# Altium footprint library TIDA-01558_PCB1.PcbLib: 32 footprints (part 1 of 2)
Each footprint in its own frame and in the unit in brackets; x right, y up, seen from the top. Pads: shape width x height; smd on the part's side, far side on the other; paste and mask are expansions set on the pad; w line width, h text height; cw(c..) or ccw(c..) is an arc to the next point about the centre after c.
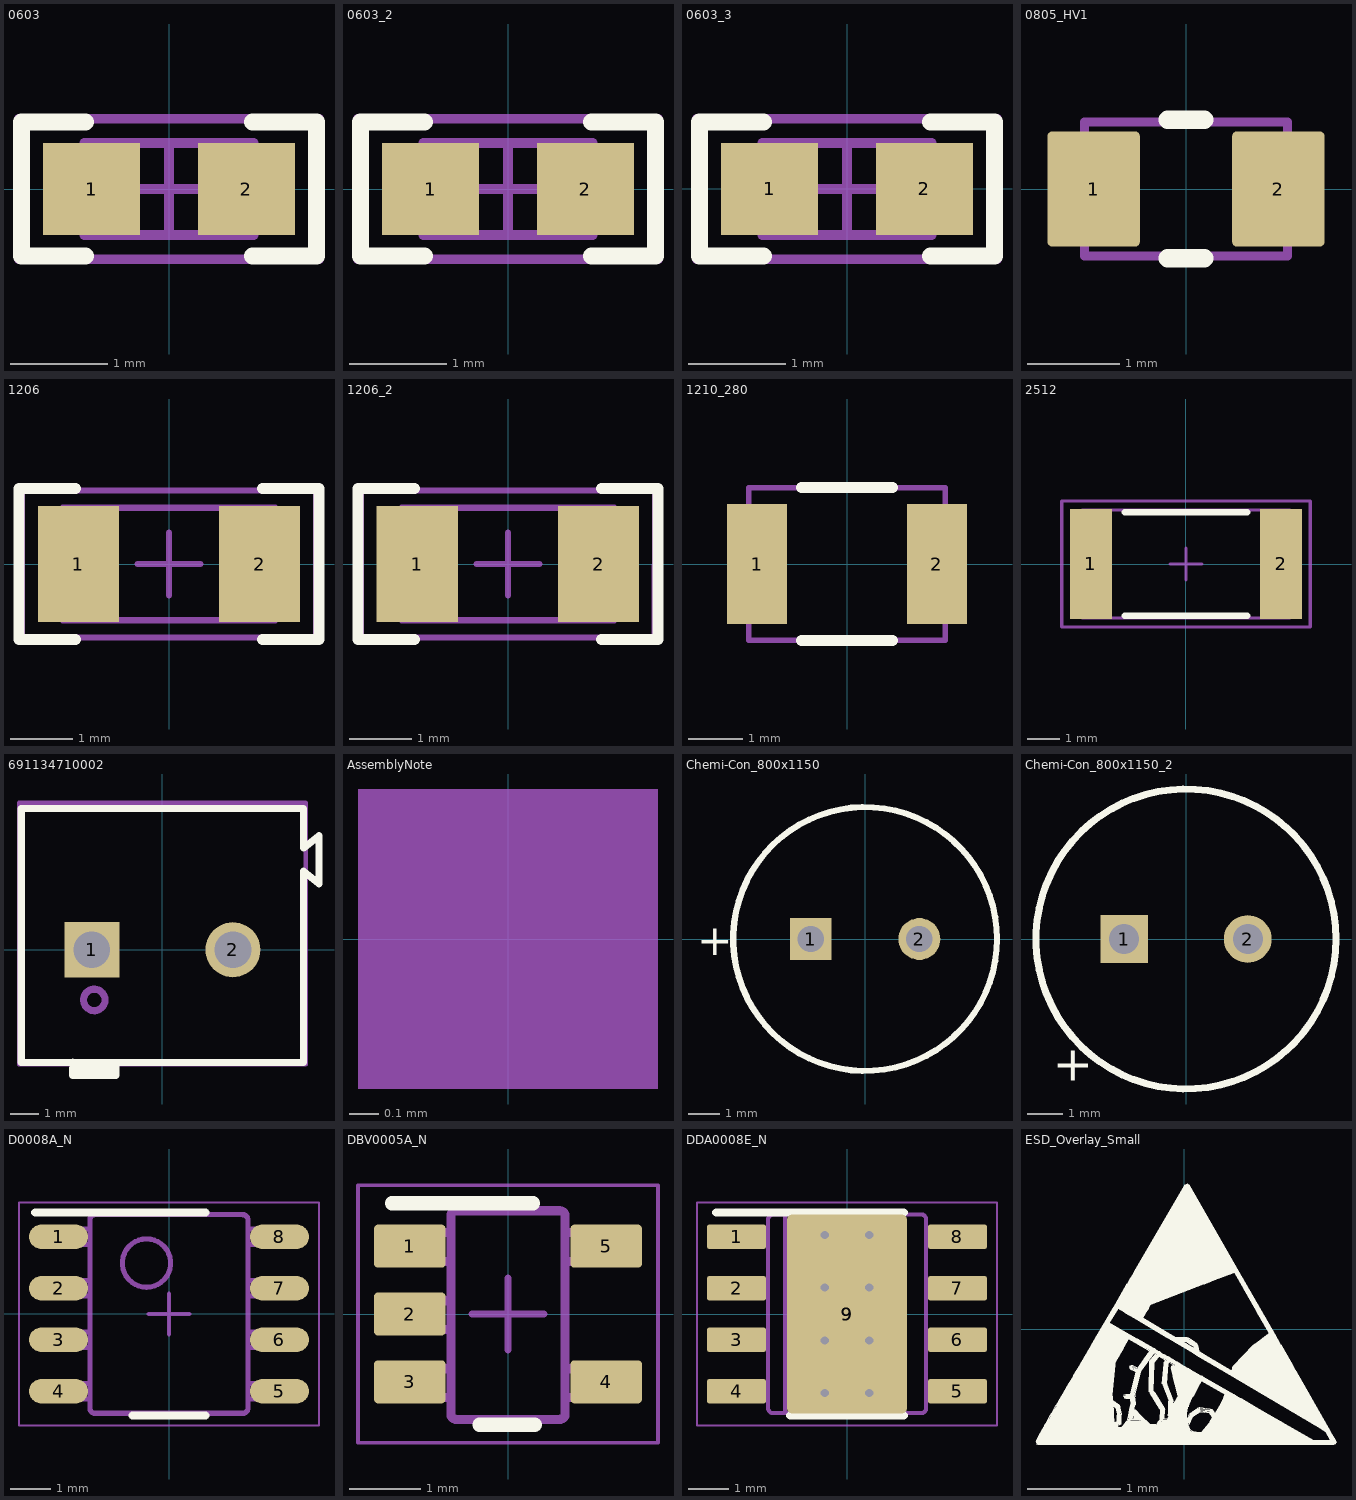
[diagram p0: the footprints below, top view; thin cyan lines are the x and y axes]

## 0603 [mm] "0603 from SM-752 data"
height 1
pads (2):
  rect 1x0.95 smd: 1(-0.8,0) 2(0.8,0)
Top Overlay:
  lines w0.178: -0.864,-0.691 -1.524,-0.691 -1.524,0.693 -0.864,0.693 ; 0.864,-0.691 1.524,-0.691 1.524,0.693 0.864,0.693
Mechanical 5:
  lines w0.1: -1.55,-0.725 1.55,-0.725 1.55,0.725 -1.55,0.725 -1.55,-0.725
  text ".Designator" at -0.933,-0.356 h0.76
Mechanical 13:
  lines w0.1: -0.55,-0.475 -0.55,0.475 ; 0.55,-0.475 0.55,0.475 ; -0.875,-0.475 -0.875,0.475 0.875,0.475 0.875,-0.475 -0.875,-0.475
Mechanical 15:
  lines w0.1: -0.475,0 0.475,0 ; 0,-0.475 0,0.475 ; -1.55,-0.725 -1.55,0.725 1.55,0.725 1.55,-0.725 -1.55,-0.725
3D body: height 1, standoff 0, extent 0.551,-0.474 0.874,0.474
3D body: height 1, standoff 0, extent -0.549,-0.474 0.549,0.474
3D body: height 1, standoff 0, extent -0.874,-0.474 -0.551,0.474

## 0603_2 [mm]
pads (2):
  rect 1x0.95 smd: 1(-0.8,0) 2(0.8,0)
Top Overlay:
  lines w0.178: -0.864,-0.691 -1.524,-0.691 -1.524,0.693 -0.864,0.693 ; 0.864,-0.691 1.524,-0.691 1.524,0.693 0.864,0.693
Mechanical 5:
  lines w0.1: -1.55,-0.725 1.55,-0.725 1.55,0.725 -1.55,0.725 -1.55,-0.725
  text ".Designator" at -0.781,-0.381 h0.76
Mechanical 13:
  lines w0.1: -0.55,-0.475 -0.55,0.475 ; 0.55,-0.475 0.55,0.475 ; -0.875,-0.475 -0.875,0.475 0.875,0.475 0.875,-0.475 -0.875,-0.475
Mechanical 15:
  lines w0.1: -0.475,0 0.475,0 ; 0,-0.475 0,0.475 ; -1.55,-0.725 -1.55,0.725 1.55,0.725 1.55,-0.725 -1.55,-0.725
3D body: height 1, standoff 0, extent 0.551,-0.474 0.874,0.474
3D body: height 1, standoff 0, extent -0.549,-0.474 0.549,0.474
3D body: height 1, standoff 0, extent -0.874,-0.474 -0.551,0.474

## 0603_3 [mm]
pads (2):
  rect 1x0.95 smd: 1(-0.8,0) 2(0.8,0)
Top Overlay:
  lines w0.178: -0.864,-0.691 -1.524,-0.691 -1.524,0.693 -0.864,0.693 ; 0.864,-0.691 1.524,-0.691 1.524,0.693 0.864,0.693
Mechanical 5:
  lines w0.1: -1.55,-0.725 1.55,-0.725 1.55,0.725 -1.55,0.725 -1.55,-0.725
  text ".Designator" at 1.016,0.381 h0.76
Mechanical 13:
  lines w0.1: -0.55,-0.475 -0.55,0.475 ; 0.55,-0.475 0.55,0.475 ; -0.875,-0.475 -0.875,0.475 0.875,0.475 0.875,-0.475 -0.875,-0.475
Mechanical 15:
  lines w0.1: -0.475,0 0.475,0 ; 0,-0.475 0,0.475 ; -1.55,-0.725 -1.55,0.725 1.55,0.725 1.55,-0.725 -1.55,-0.725
3D body: height 1, standoff 0, extent 0.551,-0.474 0.874,0.474
3D body: height 1, standoff 0, extent -0.549,-0.474 0.549,0.474
3D body: height 1, standoff 0, extent -0.874,-0.474 -0.551,0.474

## 0805_HV1 [mm] "Custom footprint based on analyzing multiple manufacturer recommendations"
height 1.45
pads (2):
  rrect10% 1x1.25 smd: 1(-1,0) 2(1,0)
Top Overlay:
  lines w0.2: -0.2,-0.75 0.2,-0.75 ; -0.2,0.75 0.2,0.75
Mechanical 5:
  lines w0.1: -1.1,-0.725 -1.1,0.725 1.1,0.725 1.1,-0.725 -1.1,-0.725
  text ".Designator" at 0.619,0.279 h0.51
3D body "0805_CapMax.stp": height 1.45, standoff 0, extent -1.1,-0.725 1.1,0.725

## 1206 [mm] "1206 from SM-752 data"
height 1.35
pads (2):
  rect 1.3x1.85 smd: 1(-1.45,0) 2(1.45,0)
Top Overlay:
  lines w0.178: -1.5,-1.21 -2.4,-1.21 -2.4,1.21 -1.5,1.21 ; 1.5,-1.21 2.4,-1.21 2.4,1.21 1.5,1.21
Mechanical 5:
  lines w0.1: -1.7,-0.9 -1.7,0.9 1.7,0.9 1.7,-0.9 -1.7,-0.9
  text ".Designator" at 0.965,0.406 h0.81
Mechanical 13:
  lines w0.1: -1.2,-0.9 -1.2,0.9 ; 1.2,-0.9 1.2,0.9 ; -1.7,-0.9 -1.7,0.9 1.7,0.9 1.7,-0.9 -1.7,-0.9
Mechanical 15:
  lines w0.1: -0.5,0 0.5,0 ; 0,-0.5 0,0.5 ; -2.35,-1.175 -2.35,1.175 2.35,1.175 2.35,-1.175 -2.35,-1.175
3D body: height 1.35, standoff 0, extent 1.201,-0.899 1.699,0.899
3D body: height 1.35, standoff 0, extent -1.199,-0.899 1.199,0.899
3D body: height 1.35, standoff 0, extent -1.699,-0.899 -1.201,0.899

## 1206_2 [mm]
pads (2):
  rect 1.3x1.85 smd: 1(-1.45,0) 2(1.45,0)
Top Overlay:
  lines w0.178: -1.5,-1.21 -2.4,-1.21 -2.4,1.21 -1.5,1.21 ; 1.5,-1.21 2.4,-1.21 2.4,1.21 1.5,1.21
Mechanical 5:
  lines w0.1: -1.7,-0.9 -1.7,0.9 1.7,0.9 1.7,-0.9 -1.7,-0.9
  text ".Designator" at -0.381,0.711 h0.81
Mechanical 13:
  lines w0.1: -1.2,-0.9 -1.2,0.9 ; 1.2,-0.9 1.2,0.9 ; -1.7,-0.9 -1.7,0.9 1.7,0.9 1.7,-0.9 -1.7,-0.9
Mechanical 15:
  lines w0.1: -0.5,0 0.5,0 ; 0,-0.5 0,0.5 ; -2.35,-1.175 -2.35,1.175 2.35,1.175 2.35,-1.175 -2.35,-1.175
3D body: height 1.35, standoff 0, extent 1.201,-0.899 1.699,0.899
3D body: height 1.35, standoff 0, extent -1.199,-0.899 1.199,0.899
3D body: height 1.35, standoff 0, extent -1.699,-0.899 -1.201,0.899

## 1210_280 [mm] "SMD, 2-Leads, Body 3.6x2.8mm, Height 2.8mm"
height 2.8
pads (2):
  rect 1.1x2.2 smd: 1(-1.65,0) 2(1.65,0)
Top Overlay:
  lines w0.2: -0.835,-1.4 0.835,-1.4 ; -0.835,1.4 0.835,1.4
Mechanical 5:
  lines w0.1: -1.8,-1.4 1.8,-1.4 1.8,1.4 -1.8,1.4 -1.8,-1.4
  text ".Designator" at 0.66,0.356 h0.8
3D body: height 2.8, standoff 0, extent 1.6,-1.4 1.8,1.4
3D body: height 2.8, standoff 0, extent -1.6,-1.4 1.6,1.4
3D body: height 2.8, standoff 0, extent -1.8,-1.4 -1.6,1.4

## 2512 [mm] "Chip Resistor, Body 6.3x3.2mm, IPC Medium Density"
height 0.71
pads (2):
  rect 1.3x3.4 smd: 1(-2.95,0) 2(2.95,0)
Top Overlay:
  lines w0.2: -1.9,-1.6 1.9,-1.6 ; -1.9,1.6 1.9,1.6
Mechanical 5:
  lines w0.1: -3.225,-1.675 -3.225,1.675 3.225,1.675 3.225,-1.675 -3.225,-1.675
  text ".Designator" at -0.889,-0.533 h1.02
Mechanical 13:
  lines w0.1: -2.463,-1.675 -2.463,1.675 ; 2.463,-1.675 2.463,1.675 ; -3.225,-1.675 -3.225,1.675 3.225,1.675 3.225,-1.675 -3.225,-1.675
Mechanical 15:
  lines w0.1: -0.5,0 0.5,0 ; 0,-0.5 0,0.5 ; -3.85,-1.95 -3.85,1.95 3.85,1.95 3.85,-1.95 -3.85,-1.95
3D body: height 0.71, standoff 0, extent 2.464,-1.674 3.224,1.674
3D body: height 0.71, standoff 0, extent -2.462,-1.674 2.462,1.674
3D body: height 0.71, standoff 0, extent -3.224,-1.674 -2.464,1.674

## 691134710002 [mm] "Serie 1347 - 5.00 mm_2 pins"
height 13
pads (2):
  rect 1.95x1.95 hole 1.3: 1(-2.5,0)
  round 1.95 hole 1.3: 2(2.5,0)
Top Overlay:
  lines w0.152: -3.175,-4.191 -3.175,-3.937 ; -1.651,-4.191 -1.651,-4
  lines w0.254: -1.651,-4.191 -3.175,-4.191 -3.175,-4.445 -1.651,-4.445 -1.651,-4 ; -5,-4 -5,5 5,5 5,3.6 5.55,4.04 5.55,2.34 5,2.78 5,-4 -5,-4
Mechanical 5:
  circle w0.254: c-2.413,-1.778 r0.381
  lines w0.152: -5.08,-4.064 -5.08,4.826 -5.08,5.207 5.08,5.207 5.08,-4.064 -5.08,-4.064
  text ".Designator" at 0.406,-0.508 h0.76
3D body "691134710002.stp": height 13.1, standoff -3.9, extent -5,-4 5.55,5

## AssemblyNote [mm] "Assembly Note"
Mechanical 5:
  rectangle: -0.508,-0.508 0.508,0.508
  text ".Designator" at -4.191,-0.508 h1.02
  text ".Comment" at 1.143,-0.508 h1.02

## Chemi-Con_800x1150 [mm] "TH, 2-Leads, Dia 8mm"
height 13
pads (2):
  rect 1.35x1.35 hole 0.85: 1(-1.75,0)
  round 1.35 hole 0.85: 2(1.75,0)
Top Overlay:
  circle w0.2: c0,0 r4.25
  text "+" at -5.416,-0.527 h1
Mechanical 5:
  circle w0.1: c0,0 r4.25
  text "+" at -5.416,-0.527 h1
  text "+" at -5.416,-0.527 h1
  text ".Designator" at 0.635,-1.27 h1.02
3D body: height 0, standoff -2.5, extent -2.048,-0.299 -1.45,0.299
3D body: height 0, standoff -2, extent 1.452,-0.299 2.05,0.299
3D body "KZN_800x1150.stp": height 13.01, standoff -4, extent -4.25,-4.249 4.26,4.25

## Chemi-Con_800x1150_2 [mm]
pads (2):
  rect 1.35x1.35 hole 0.85: 1(-1.75,0)
  round 1.35 hole 0.85: 2(1.75,0)
Top Overlay:
  circle w0.2: c0,0 r4.25
  text "+" at -3.782,-4.013 h1
Mechanical 5:
  circle w0.1: c0,0 r4.25
  text "+" at -3.782,-4.013 h1
  text "+" at -3.782,-4.013 h1
  text ".Designator" at -1.6,-0.4 h1.02
3D body: height 0, standoff -2.5, extent -2.047,-0.299 -1.45,0.3
3D body: height 0, standoff -2, extent 1.453,-0.299 2.05,0.3
3D body "KZN_800x1150.stp": height 13.01, standoff -4, extent -4.217,-4.243 4.244,4.243

## D0008A_N [mm] "SOIC, 8-Leads, Body 4.9x3.9mm, Pitch 1.27mm, IPC Medium Density"
height 1.75
pads (8):
  oval 1.45x0.6 smd: 1(-2.725,1.905) 2(-2.725,0.635) 3(-2.725,-0.635) 4(-2.725,-1.905) 5(2.725,-1.905) 6(2.725,-0.635) 7(2.725,0.635) 8(2.725,1.905)
Top Overlay:
  lines w0.2: -3.3,2.5 0.9,2.5 ; -0.9,-2.5 0.9,-2.5
Mechanical 5:
  lines w0.127: -2.375,-2.095 -2.375,-1.715 ; -2.375,-2.095 -2.589,-2.095 -3.002,-2.095 -3.002,-1.715 -2.589,-1.715 -2.375,-1.715 ; -2.375,-2.095 -1.995,-2.095 -1.952,-2.095 -1.952,-1.715 -1.995,-1.715 -2.375,-1.715 ; -2.375,-0.825 -2.375,-0.445 ; -2.375,-0.825 -2.589,-0.825 -3.002,-0.825 -3.002,-0.445 -2.589,-0.445 -2.375,-0.445 ; -2.375,-0.825 -1.995,-0.825 -1.952,-0.825 -1.952,-0.445 -1.995,-0.445 -2.375,-0.445 ; -2.375,0.445 -2.375,0.825 ; -2.375,0.445 -2.589,0.445 -3.002,0.445 -3.002,0.825 -2.589,0.825 -2.375,0.825 ; -2.375,0.445 -1.995,0.445 -1.952,0.445 -1.952,0.825 -1.995,0.825 -2.375,0.825 ; -2.375,1.715 -2.375,2.095 ; -2.375,1.715 -2.589,1.715 -3.002,1.715 -3.002,2.095 -2.589,2.095 -2.375,2.095 ; -2.375,1.715 -1.995,1.715 -1.952,1.715 -1.952,2.095 -1.995,2.095 -2.375,2.095 ; -0.332,-2.45 -0.182,-2.45 ; -0.332,-2.45 -0.182,-2.45 ; -0.332,-2.45 -1.825,-2.45 -1.826,-2.45 cw(c-1.825,-2.323) -1.952,-2.324 -1.952,-2.323 -1.952,2.323 -1.952,2.324 cw(c-1.825,2.323) -1.826,2.45 -1.825,2.45 -0.332,2.45 ; -0.332,2.45 -0.182,2.45 ; -0.332,2.45 -0.182,2.45 ; -0.182,-2.45 0.178,-2.45 ; -0.182,2.45 0.178,2.45 ; 0.178,-2.45 0.328,-2.45 ; 0.178,-2.45 0.328,-2.45 ; 0.178,2.45 0.328,2.45 ; 0.178,2.45 0.328,2.45 ; 0.328,-2.45 1.821,-2.45 1.822,-2.45 ccw(c1.821,-2.323) 1.948,-2.324 1.948,-2.323 1.948,2.323 1.948,2.324 ccw(c1.821,2.323) 1.822,2.45 1.821,2.45 0.328,2.45 ; 2.371,-2.095 2.371,-1.715 ; 2.371,-2.095 1.991,-2.095 1.948,-2.095 1.948,-1.715 1.991,-1.715 2.371,-1.715 ; 2.371,-2.095 2.585,-2.095 2.998,-2.095 2.998,-1.715 2.585,-1.715 2.371,-1.715 ; 2.371,-0.825 2.371,-0.445 ; 2.371,-0.825 1.991,-0.825 1.948,-0.825 1.948,-0.445 1.991,-0.445 2.371,-0.445 ; 2.371,-0.825 2.585,-0.825 2.998,-0.825 2.998,-0.445 2.585,-0.445 2.371,-0.445 ; 2.371,0.445 2.371,0.825 ; 2.371,0.445 1.991,0.445 1.948,0.445 1.948,0.825 1.991,0.825 2.371,0.825 ; 2.371,0.445 2.585,0.445 2.998,0.445 2.998,0.825 2.585,0.825 2.371,0.825 ; 2.371,1.715 2.371,2.095 ; 2.371,1.715 1.991,1.715 1.948,1.715 1.948,2.095 1.991,2.095 2.371,2.095 ; 2.371,1.715 2.585,1.715 2.998,1.715 2.998,2.095 2.585,2.095 2.371,2.095 ; -0.555,0.659 ccw(c-0.555,1.256) -0.555,1.853 ccw(c-0.555,1.256) -0.555,0.659
  text ".Designator" at -0.813,-0.914 h0.89
Mechanical 15:
  lines w0.05: -3.7,-2.75 -3.7,2.75 3.7,2.75 3.7,-2.75 -3.7,-2.75
  lines w0.1: -0.5,0 0.5,0 ; 0,-0.5 0,0.5
3D body "D0008A.stp": height 1.63, standoff 0, extent -3,-2.45 3,2.45

## DBV0005A_N [mm] "SOT23, 5-Leads, Body 2.9x1.6mm, Pitch 0.95mm, Lead Span 2.8mm, IPC Medium Density"
height 1.45
pads (5):
  rrect17% 1x0.6 smd: 1(-1.375,0.95) 2(-1.375,0) 3(-1.375,-0.95) 4(1.375,-0.95) 5(1.375,0.95)
Top Overlay:
  lines w0.2: -1.625,1.55 0.35,1.55 ; -0.4,-1.55 0.375,-1.55
Mechanical 5:
  lines w0.127: -0.801,1.371 cw(c-0.725,1.37) -0.725,1.446 ; -0.801,1.37 -0.801,-1.399 -0.801,-1.4 ccw(c-0.725,-1.399) -0.725,-1.475 ; -0.801,1.37 -0.801,1.371 ; -0.725,-1.475 -0.725,-1.475 ; -0.725,-1.475 0.723,-1.475 0.724,-1.475 ccw(c0.723,-1.399) 0.799,-1.4 0.799,-1.399 0.799,1.37 ; -0.725,1.446 0.723,1.446 0.724,1.446 cw(c0.723,1.37) 0.799,1.371 ; -0.725,1.446 -0.725,1.446 ; 0.799,1.37 0.799,1.371 ; -1.423,-1.167 -1.199,-1.167 -1.105,-1.167 -1.088,-1.167 -0.835,-1.167 -0.801,-1.167 -0.801,-0.767 -0.835,-0.767 -1.088,-0.767 -1.105,-0.767 -1.199,-0.767 -1.423,-0.767 -1.423,-1.167 ; -1.423,-0.215 -1.199,-0.215 -1.105,-0.215 -1.088,-0.215 -0.835,-0.215 -0.801,-0.215 -0.801,0.186 -0.835,0.186 -1.088,0.186 -1.105,0.186 -1.199,0.186 -1.423,0.186 -1.423,-0.215 ; -1.423,0.738 -1.199,0.738 -1.105,0.738 -1.088,0.738 -0.835,0.738 -0.801,0.738 -0.801,1.138 -0.835,1.138 -1.088,1.138 -1.105,1.138 -1.199,1.138 -1.423,1.138 -1.423,0.738 ; 0.799,-1.167 0.799,-0.767 0.834,-0.767 1.087,-0.767 1.103,-0.767 1.198,-0.767 1.422,-0.767 1.422,-1.167 1.198,-1.167 1.103,-1.167 1.087,-1.167 0.834,-1.167 0.799,-1.167 ; 0.799,0.738 0.799,1.138 0.834,1.138 1.087,1.138 1.103,1.138 1.198,1.138 1.422,1.138 1.422,0.738 1.198,0.738 1.103,0.738 1.087,0.738 0.834,0.738 0.799,0.738
  text ".Designator" at 0.254,-0.457 h0.51
Mechanical 15:
  lines w0.05: -2.1,-1.8 2.1,-1.8 2.1,1.8 -2.1,1.8 -2.1,-1.8
  lines w0.1: -0.5,0 0.5,0 ; 0,-0.5 0,0.5
3D body "DBV0005A.stp": height 1.09, standoff 0, extent -1.422,-1.46 1.422,1.461

## DDA0008E_N [mm]
height 1.7
pads (11):
  rrect17% 1.45x0.6 smd: 1(-2.725,1.905) 2(-2.725,0.635) 3(-2.725,-0.635) 4(-2.725,-1.905) 5(2.725,-1.905) 6(2.725,-0.635) 7(2.725,0.635) 8(2.725,1.905)
  rrect7% 2.95x4.9 smd: 9(0,0)
  rrect50% 2.4x3.1 on Top Paste: 9(0,0)
  rrect50% 2.4x3.1 on Top Solder: 9(0,0)
via 0.55,-1.95 diameter 0.5 hole 0.2
via -0.55,-1.95 diameter 0.5 hole 0.2
via -0.55,1.95 diameter 0.5 hole 0.2
via 0.55,1.95 diameter 0.5 hole 0.2
via 0.55,-0.65 diameter 0.5 hole 0.2
via -0.55,-0.65 diameter 0.5 hole 0.2
via 0.55,0.65 diameter 0.5 hole 0.2
via -0.55,0.65 diameter 0.5 hole 0.2
Top Overlay:
  lines w0.2: -3.225,2.5 1.4,2.5 ; -1.4,-2.5 1.4,-2.5
Mechanical 5:
  lines w0.1: -1.524,-2.447 -1.524,2.456 ; -1.82,-2.447 cw(c-1.819,-2.32) -1.946,-2.321 -1.946,-2.32 -1.946,2.329 -1.946,2.33 cw(c-1.819,2.329) -1.82,2.456 ; -1.819,-2.447 1.826,-2.447 1.827,-2.447 ccw(c1.826,-2.32) 1.953,-2.321 1.953,-2.32 1.953,2.329 ; -1.82,-2.447 -1.819,-2.447 ; -1.82,2.456 -1.819,2.456 ; -1.819,2.456 1.826,2.456 1.827,2.456 cw(c1.826,2.329) 1.953,2.33 ; 1.953,2.329 1.953,2.33 ; -2.975,-2.091 -2.975,-1.71 -2.614,-1.71 -2.497,-1.71 -2.473,-1.71 -2.144,-1.71 -1.946,-1.71 -1.946,-2.091 -2.144,-2.091 -2.473,-2.091 -2.497,-2.091 -2.614,-2.091 -2.975,-2.091 ; -2.975,-0.821 -2.975,-0.44 -2.614,-0.44 -2.497,-0.44 -2.473,-0.44 -2.144,-0.44 -1.946,-0.44 -1.946,-0.821 -2.144,-0.821 -2.473,-0.821 -2.497,-0.821 -2.614,-0.821 -2.975,-0.821 ; -2.975,0.449 -2.975,0.83 -2.614,0.83 -2.497,0.83 -2.473,0.83 -2.144,0.83 -1.946,0.83 -1.946,0.449 -2.144,0.449 -2.473,0.449 -2.497,0.449 -2.614,0.449 -2.975,0.449 ; -2.975,1.719 -2.975,2.1 -2.614,2.1 -2.497,2.1 -2.473,2.1 -2.144,2.1 -1.946,2.1 -1.946,1.719 -2.144,1.719 -2.473,1.719 -2.497,1.719 -2.614,1.719 -2.975,1.719 ; -0.632,1.16 ccw(c-0.632,1.478) -0.632,1.795 ccw(c-0.632,1.478) -0.632,1.16 ; 1.953,-2.091 1.953,-1.71 2.15,-1.71 2.479,-1.71 2.503,-1.71 2.621,-1.71 2.981,-1.71 2.981,-2.091 2.621,-2.091 2.503,-2.091 2.479,-2.091 2.15,-2.091 1.953,-2.091 ; 1.953,-0.821 1.953,-0.44 2.15,-0.44 2.479,-0.44 2.503,-0.44 2.621,-0.44 2.981,-0.44 2.981,-0.821 2.621,-0.821 2.503,-0.821 2.479,-0.821 2.15,-0.821 1.953,-0.821 ; 1.953,0.449 1.953,0.83 2.15,0.83 2.479,0.83 2.503,0.83 2.621,0.83 2.981,0.83 2.981,0.449 2.621,0.449 2.503,0.449 2.479,0.449 2.15,0.449 1.953,0.449 ; 1.953,1.719 1.953,2.1 2.15,2.1 2.479,2.1 2.503,2.1 2.621,2.1 2.981,2.1 2.981,1.719 2.621,1.719 2.503,1.719 2.479,1.719 2.15,1.719 1.953,1.719
  text ".Designator" at -0.422,0.749 h1.85
Mechanical 15:
  lines w0.05: -3.7,-2.75 3.7,-2.75 3.7,2.75 -3.7,2.75 -3.7,-2.75
  lines w0.1: -0.5,0 0.5,0 ; 0,-0.5 0,0.5
3D body "DDA0008E.stp": height 1.57, standoff 0, extent -3,-2.45 3,2.45

## ESD_Overlay_Small [mm]
Top Overlay:
  drawing of 901 lines, arcs and shapes, not listed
